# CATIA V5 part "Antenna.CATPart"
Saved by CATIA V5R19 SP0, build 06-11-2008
Part number: Antenna
Bounding box of the stored display mesh (mm): x 95.72 to 104.957, y -9.594 to -1.526, z 0 to 46
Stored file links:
  C:\Users\sisca\Desktop\HELTEC_CASE\Antenna.CATPart
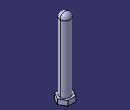
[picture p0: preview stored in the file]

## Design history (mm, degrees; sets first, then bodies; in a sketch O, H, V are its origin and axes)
Body1 (main body)
  Sketch1 on xy-plane, origin (0, 0, 0), H (1, 0, 0), V (0, 1, 0)
    point P1 (100.3383, -5.5601)
    point P2 (102.7065, -9.5255)
    point P3 (104.9566, -5.4919)
    point P4 (102.5884, -1.5264)
    point P5 (97.9701, -1.5946)
    point P6 (95.72, -5.6283)
    point P7 (98.0882, -9.5937)
    point P8 (103.8316, -7.5087)
    line L1 (102.7065, -9.5255) -> (104.9566, -5.4919)
    line L2 (104.9566, -5.4919) -> (102.5884, -1.5264)
    line L3 (102.5884, -1.5264) -> (97.9701, -1.5946)
    line L4 (97.9701, -1.5946) -> (95.72, -5.6283)
    line L5 (95.72, -5.6283) -> (98.0882, -9.5937)
    line L6 (98.0882, -9.5937) -> (102.7065, -9.5255)
    construction line L7 (100.3383, -5.5601) -> (103.8316, -7.5087)
    construction circle A1 centre (100.3383, -5.5601) radius 4.6188
    construction arc A2 centre (95.72, -5.6283) radius 4.6188 from (97.9701, -1.5946) to (98.0882, -9.5937) cw
    construction arc A3 centre (104.9566, -5.4919) radius 4.6188 from (102.5884, -1.5264) to (102.7065, -9.5255) ccw
    distance L3 L6 = 8
    coincidence: A1 P2, A1 P3, A1 P4, A1 P5, A1 P6, A1 P7, A2 P1, A3 P1
    midpoint: P8 L1
    parallelism: L1 L4
  Pad1: profile Sketch1, direction (0, 0, 1), length 3
  Sketch2 on end face of Pad1, origin (0, 0, 3), H (1, 0, 0), V (0, 1, 0)
    circle A1 centre (100.3195, -5.5603) radius 3
    point P1 (100.3195, -5.5603)
    reference projected line E1 (102.5884, -1.5264) -> (97.9701, -1.5946) from edge [face of Pad1 from Sketch1.L3 | end face of Pad1]
    reference projected point E2 (95.72, -5.6283) from vertex [face of Pad1 from Sketch1.L5 | end face of Pad1 | face of Pad1 from Sketch1.L4]
    distance P1 E1 = 4
    distance P1 E2 = 4.6
    radius A1 = 3
  Pad2: profile Sketch2, direction (0, 0, 1), length 43
  Fillet1: radius 3, on edge [face of Pad2 from Sketch2.A1 | end face of Pad2]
